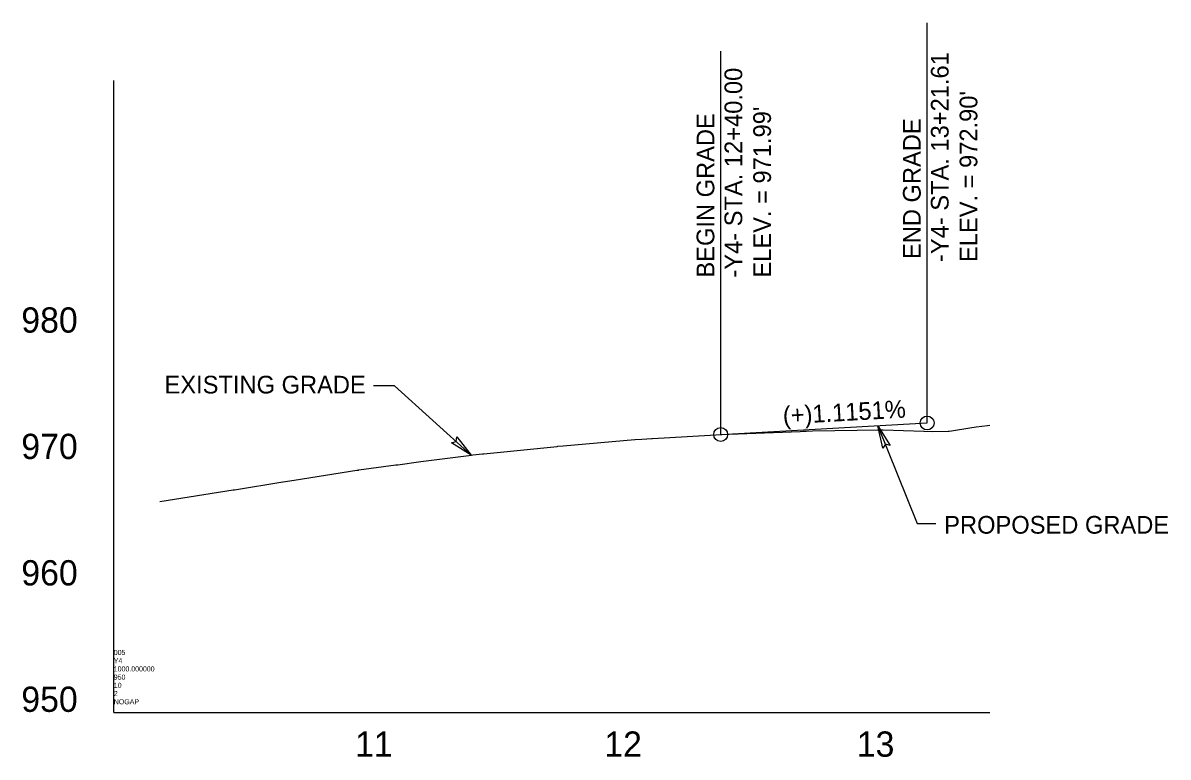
# Model space of a CAD drawing. Extents: x 1615624 to 1632571, y 894455 to 913418.
# Drawn here: x 1627781.9 to 1628234.7, y 897632.9 to 897923.3 of the extents above; entities that cross this region are included whole.
import ezdxf

# ---------------------------------------------------------------- set-up
doc = ezdxf.new("R2010")
doc.units = 0
for name, color, linetype in [('Exist Profile Cell', 7, 'Continuous'), ('Exist Vertical Profile Ground Line', 7, 'Continuous'), ('Exist Vertical Profile Horizontal Axis Label Major', 7, 'Continuous'), ('Exist Vertical Profile Vertical Axis Label', 7, 'Continuous'), ('Prop Terminator CELL', 7, 'Continuous'), ('Prop Vertical Profile Grade', 7, 'Continuous'), ('Prop Vertical Profile Grade Label', 7, 'Continuous'), ('Prop VPI Label', 7, 'Continuous')]:
    doc.layers.add(name, color=color, linetype=linetype)

msp = doc.modelspace()

# ---------------------------------------------------------------- linework, layer by layer
at = {"layer": 'Exist Profile Cell'}
for q in [(1627817.82, 897900.53), (1628164.2, 897650.53), (1627817.82, 897650.53)]:
    msp.add_line((1627817.82, 897650.53), q, dxfattribs=at)
at = {"layer": 'Exist Vertical Profile Ground Line'}
msp.add_lwpolyline([(1627836.02, 897734.05), (1627864.96, 897738.56), (1627865.56, 897738.66), (1627865.61, 897738.67), (1627884.6, 897741.71), (1627884.69, 897741.72), (1627884.74, 897741.73), (1627884.79, 897741.73), (1627889.1, 897742.43), (1627913.87, 897746.32), (1627914.6, 897746.44), (1627914.73, 897746.46), (1627929.36, 897748.43), (1627930.1, 897748.53), (1627939.23, 897749.75), (1627959.21, 897752.38), (1627959.77, 897752.46), (1627959.86, 897752.4), (1627963.67, 897752.79), (1627964.2, 897752.86), (1627993.21, 897755.8), (1627993.44, 897755.82), (1627995.55, 897755.98), (1628023.89, 897758.46), (1628023.94, 897758.46), (1628026.67, 897758.64), (1628030.54, 897758.87), (1628030.82, 897758.88), (1628060.53, 897760.66), (1628060.67, 897760.66), (1628061.16, 897760.67), (1628089.23, 897761.74), (1628090.6, 897761.8), (1628090.7, 897761.79), (1628091.63, 897761.82), (1628094.18, 897761.88), (1628120.57, 897762.37), (1628121.72, 897762.39), (1628122.03, 897762.39), (1628138.1, 897761.78), (1628138.32, 897761.78), (1628141.63, 897761.73), (1628147.81, 897761.8), (1628148.03, 897761.79), (1628148.15, 897761.79), (1628149.1, 897761.96), (1628156.32, 897763.08), (1628158.8, 897763.56), (1628163.29, 897764.1), (1628164.2, 897764.23)], dxfattribs=at)
at = {"layer": 'Prop Terminator CELL'}
for points in [[(1628121.93, 897755.03), (1628120.02, 897763.97), (1628124.87, 897756.16), (1628122.96, 897756.63)], [(1627953.45, 897759.55), (1627959.09, 897752.36), (1627951.3, 897757.24), (1627953.23, 897757.66)]]:
    msp.add_lwpolyline(points, close=True, dxfattribs=at)
at = {"layer": 'Prop Vertical Profile Grade'}
msp.add_line((1628057.82, 897760.49), (1628139.43, 897765.05), dxfattribs=at)
at = {"layer": 'Prop VPI Label'}
for p, q in [((1628139.43, 897765.05), (1628139.43, 897923.3)), ((1628057.82, 897760.49), (1628057.82, 897912.12)), ((1627928.77, 897779.74), (1627920.51, 897779.74)), ((1627959.09, 897752.36), (1627928.77, 897779.74)), ((1628120.02, 897763.97), (1628135.51, 897725.24)), ((1628135.51, 897725.24), (1628142.92, 897725.24))]:
    msp.add_line(p, q, dxfattribs=at)
for centre in [(1628139.43, 897765.05), (1628057.82, 897760.49)]:
    msp.add_circle(centre, 2.75, dxfattribs=at)

# ---------------------------------------------------------------- texts
at = {"layer": 'Exist Profile Cell'}
for s, p in [('Y4', (1627817.82, 897670.03)), ('005', (1627817.82, 897673.28)), ('1000.000000', (1627817.82, 897666.78)), ('950', (1627817.82, 897663.53)), ('10', (1627817.82, 897660.28)), ('2', (1627817.82, 897657.03)), ('NOGAP', (1627817.82, 897653.78))]:
    msp.add_text(s, height=2, dxfattribs=at).set_placement(p)
at = {"layer": 'Exist Vertical Profile Horizontal Axis Label Major'}
for s, p in [('11', (1627913.24, 897633.03)), ('12', (1628011.79, 897633.03)), ('13', (1628111.63, 897633.03))]:
    msp.add_text(s, height=10, dxfattribs=at).set_placement(p)
at = {"layer": 'Exist Vertical Profile Vertical Axis Label'}
for s, p in [('980', (1627781.25, 897800.78)), ('970', (1627781.25, 897750.78)), ('960', (1627781.25, 897700.78)), ('950', (1627781.25, 897650.78))]:
    msp.add_text(s, height=10, dxfattribs=at).set_placement(p)
at = {"layer": 'Prop Vertical Profile Grade Label'}
msp.add_text('(+)1.1151%', height=7, rotation=3.1953, dxfattribs=at).set_placement((1628082.58, 897764.48))
at = {"layer": 'Prop VPI Label'}
for s, p in [('-Y4- STA. 13+21.61', (1628147.94, 897828.72)), ('-Y4- STA. 12+40.00', (1628066.33, 897822.56)), ("ELEV. = 972.90'", (1628159.31, 897828.72)), ("ELEV. = 971.99'", (1628077.7, 897822.56)), ('BEGIN GRADE', (1628055.29, 897822.56)), ('END GRADE', (1628136.9, 897829.9))]:
    msp.add_text(s, height=7, rotation=90, dxfattribs=at).set_placement(p)
for s, p in [('EXISTING GRADE', (1627837.88, 897776.71)), ('PROPOSED GRADE', (1628146.2, 897721.27))]:
    msp.add_text(s, height=7, dxfattribs=at).set_placement(p)

doc.saveas('drawing.dxf')
